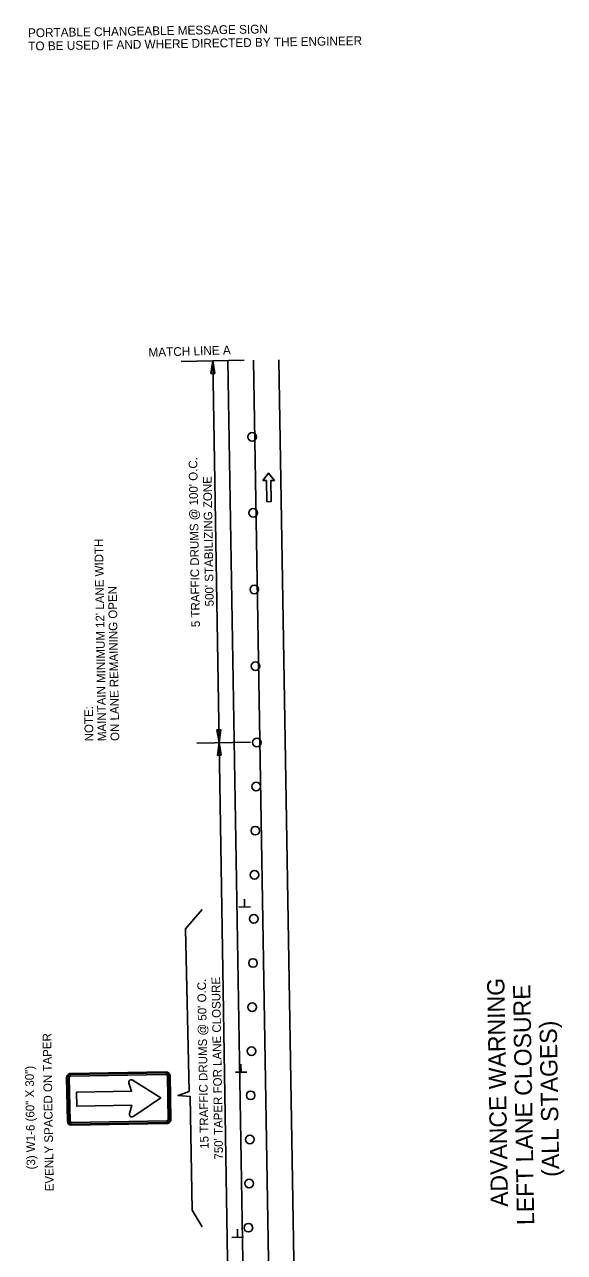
# Model space of a CAD drawing. Extents: x 1676639 to 1677883, y 226447 to 231777.
# Drawn here: x 1677049 to 1677424, y 227310 to 228165 of the extents above; entities that cross this region are included whole.
import ezdxf

# ---------------------------------------------------------------- set-up
doc = ezdxf.new("R2010")
doc.units = 0
for name, color, linetype in [('Default', 7, 'Continuous'), ('P_TC_Signs_Permanent', 7, 'Continuous'), ('R_Annotation', 7, 'Continuous'), ('R_MOT', 7, 'Continuous')]:
    doc.layers.add(name, color=color, linetype=linetype)

msp = doc.modelspace()

# ---------------------------------------------------------------- linework, layer by layer
at = {"layer": 'Default'}
for p, q in [((1677157.57, 227930.51), (1677201.48, 227931.24)), ((1677178.34, 227921.98), (1677179.53, 227930.87)), ((1677179.53, 227930.87), (1677183.93, 227664.92)), ((1677179.53, 227930.87), (1677181, 227922.03)), ((1677202.18, 227204.12), (1677190.13, 227931.05)), ((1677219.91, 227204.42), (1677207.86, 227931.34)), ((1677237.64, 227204.71), (1677225.59, 227931.64)), ((1677181, 227922.03), (1677178.34, 227921.98)), ((1677182.46, 227673.77), (1677185.12, 227673.81)), ((1677183.93, 227664.92), (1677182.46, 227673.77)), ((1677185.12, 227673.81), (1677183.93, 227664.92)), ((1677168.59, 227664.67), (1677205.89, 227665.29)), ((1677182.75, 227656.04), (1677183.93, 227664.92)), ((1677183.93, 227664.92), (1677191.58, 227203.95)), ((1677183.93, 227664.92), (1677185.41, 227656.08)), ((1677185.41, 227656.08), (1677182.75, 227656.04)), ((1677201.74, 227550.5), (1677201.65, 227555.95)), ((1677197.78, 227550.32), (1677205.76, 227550.45)), ((1677195.33, 227435.3), (1677203.31, 227435.44)), ((1677199.3, 227435.49), (1677199.21, 227440.93)), ((1677196.86, 227320.47), (1677196.77, 227325.92)), ((1677192.89, 227320.29), (1677200.87, 227320.42))]:
    msp.add_line(p, q, dxfattribs=at)
msp.add_lwpolyline([(1677172.27, 227327.62), (1677165.12, 227339.32), (1677163.81, 227418.51), (1677155.46, 227419.07), (1677163.06, 227421.97), (1677160.48, 227535.19), (1677172.08, 227548.59)], dxfattribs=at)
for centre in [(1677207, 227877.96), (1677207.61, 227825.06), (1677208.49, 227771.6), (1677209.38, 227718.13), (1677210.26, 227665.06), (1677209.72, 227634.33), (1677209.18, 227603.6), (1677208.64, 227572.87), (1677208.1, 227542.14), (1677207.57, 227511.41), (1677207.03, 227480.68), (1677206.49, 227449.95), (1677205.95, 227419.22), (1677205.41, 227388.5), (1677204.88, 227357.77), (1677204.34, 227327.04)]:
    msp.add_circle(centre, 3, dxfattribs=at)
at = {"layer": 'P_TC_Signs_Permanent'}
for p, q in [((1677080.62, 227434.45), (1677146.98, 227435.55)), ((1677080.63, 227433.7), (1677147, 227434.8)), ((1677080.65, 227432.57), (1677147.02, 227433.68)), ((1677078.36, 227401.22), (1677077.85, 227431.59)), ((1677079.11, 227401.23), (1677078.6, 227431.6)), ((1677080.23, 227401.25), (1677079.73, 227431.62)), ((1677147.97, 227432.75), (1677148.47, 227402.38)), ((1677149.09, 227432.77), (1677149.6, 227402.4)), ((1677149.84, 227432.78), (1677150.35, 227402.41)), ((1677147.55, 227401.43), (1677081.18, 227400.33)), ((1677147.57, 227400.3), (1677081.2, 227399.2)), ((1677147.58, 227399.55), (1677081.21, 227398.45))]:
    msp.add_line(p, q, dxfattribs=at)
for points in [[(1677121.57, 227406.49), (1677123.2, 227412.28), (1677084.93, 227411.64), (1677084.77, 227421.39), (1677123.04, 227422.03), (1677121.19, 227427.75)], [(1677124.15, 227429.61), (1677143.35, 227417.49), (1677124.55, 227404.77)]]:
    msp.add_lwpolyline(points, dxfattribs=at)
for centre, radius, start, end in [((1677080.66, 227431.64), 2.81, 90.94971, 180.94971), ((1677080.66, 227431.64), 2.06, 90.94971, 180.94971), ((1677147.03, 227432.74), 2.81, 0.94971, 90.94971), ((1677147.03, 227432.74), 2.06, 0.94971, 90.94971), ((1677147.03, 227432.74), 0.938, 0.94971, 90.94971), ((1677080.66, 227431.64), 0.938, 90.94971, 180.94971), ((1677122.91, 227428.27), 1.8, 57.47423, 196.91879), ((1677164.2, 227493.02), 75, 237.47423, 237.72111), ((1677081.17, 227401.27), 2.81, 180.94971, 270.94971), ((1677081.17, 227401.27), 2.06, 180.94971, 270.94971), ((1677081.17, 227401.27), 0.937, 180.94971, 270.94971), ((1677123.28, 227406.03), 1.76, 164.98063, 304.35028), ((1677166.59, 227342.66), 75, 124.09274, 124.35028), ((1677147.53, 227402.37), 0.938, 270.94971, 0.94971), ((1677147.53, 227402.37), 2.06, 270.94971, 0.94971), ((1677147.53, 227402.37), 2.81, 270.94971, 0.94971)]:
    msp.add_arc(centre, radius, start, end, dxfattribs=at)
at = {"layer": 'R_MOT'}
msp.add_lwpolyline([(1677214.46, 227847.43), (1677218.38, 227852.68), (1677222.46, 227847.55), (1677219.96, 227847.51), (1677220.2, 227832.8), (1677217.2, 227832.75), (1677216.96, 227847.46)], close=True, dxfattribs=at)

# ---------------------------------------------------------------- texts
at = {"layer": 'Default'}
for s, p in [('PORTABLE CHANGEABLE MESSAGE SIGN', (1677051.07, 228156.26)), ('TO BE USED IF AND WHERE DIRECTED BY THE ENGINEER', (1677051.22, 228147.03))]:
    msp.add_text(s, height=6.1199, rotation=0.94971, dxfattribs=at).set_placement(p)
at = {"layer": 'R_Annotation'}
for s, height, rotation, p in [('     MATCH LINE A', 6.1199, 1.75564, (1677123.53, 227933.33)), ("5 TRAFFIC DRUMS @ 100' O.C.", 6, 90.94971, (1677170.69, 227745.43)), ("500' STABILIZING ZONE", 6, 90.94971, (1677180.28, 227759.92)), ("MAINTAIN MINIMUM 12' LANE WIDTH", 6, 90.94971, (1677105.5, 227666.01)), ('ON LANE REMAINING OPEN', 6, 90.94971, (1677114.5, 227666.16)), ('NOTE:', 6, 90.94971, (1677096.5, 227665.86)), ("15 TRAFFIC DRUMS @ 50' O.C.", 6, 90.94971, (1677176.71, 227382.05)), ("750' TAPER FOR LANE CLOSURE", 6, 90.94971, (1677186.77, 227374.51)), ('ADVANCE WARNING', 12, 90.94971, (1677385.1, 227341.58)), ('LEFT LANE CLOSURE', 12, 90.94971, (1677403.31, 227328.98)), ('(ALL STAGES)', 12, 90.94971, (1677420.75, 227362.54)), ('EVENLY SPACED ON TAPER', 6, 90.95726, (1677068.95, 227352.48)), ('(3) W1-6 (60" X 30")', 6, 90.95726, (1677056.09, 227367.65))]:
    msp.add_text(s, height=height, rotation=rotation, dxfattribs=at).set_placement(p)

doc.saveas('drawing.dxf')
